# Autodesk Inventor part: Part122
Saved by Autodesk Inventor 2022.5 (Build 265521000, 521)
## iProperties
Created: 2024-12
Part Number: Part122
Material: Generic
Document SubType Name: Modeling
Designer: AdminForWorker
Density: 1 g/cm^3
Appearance: Default
Author: AdminForWorker
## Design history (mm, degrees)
feature "Body1"
feature "Body2"
feature "Body3"
body "Solid1"
body "Solid2"
body "Solid3"
